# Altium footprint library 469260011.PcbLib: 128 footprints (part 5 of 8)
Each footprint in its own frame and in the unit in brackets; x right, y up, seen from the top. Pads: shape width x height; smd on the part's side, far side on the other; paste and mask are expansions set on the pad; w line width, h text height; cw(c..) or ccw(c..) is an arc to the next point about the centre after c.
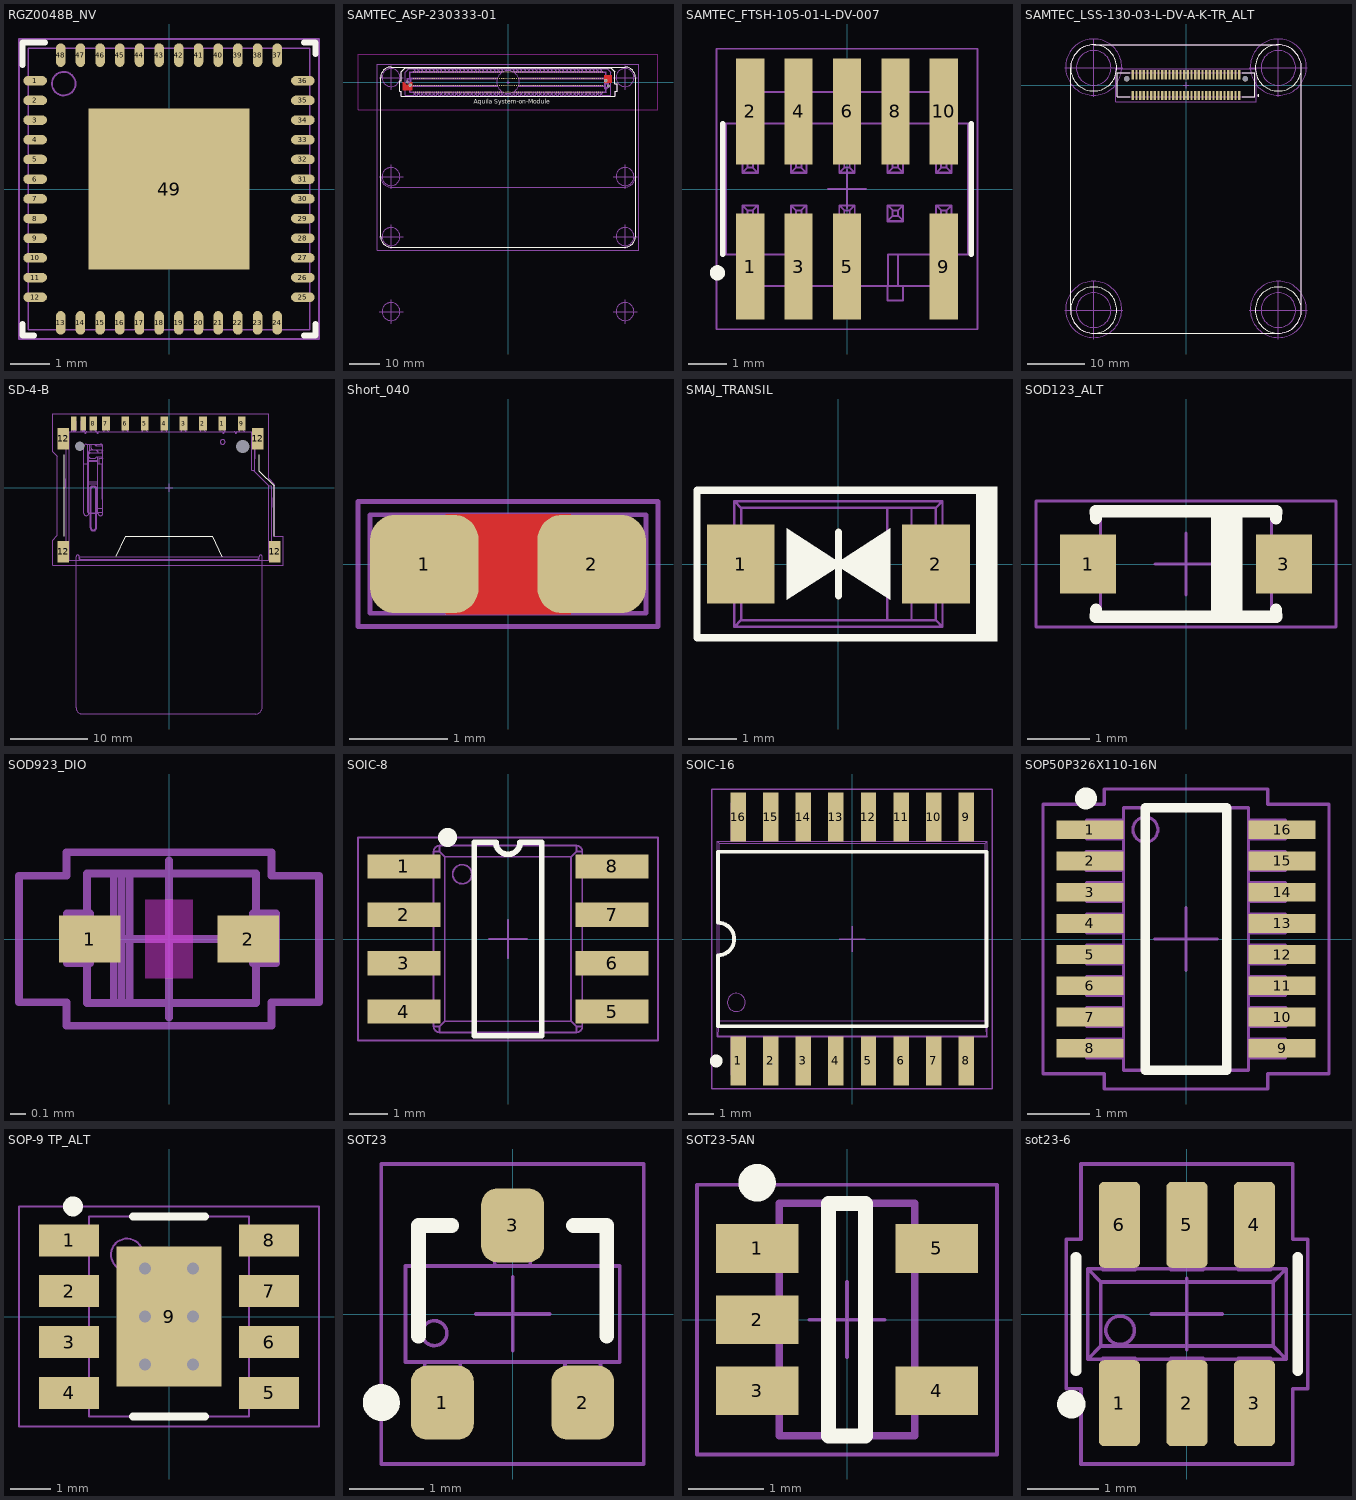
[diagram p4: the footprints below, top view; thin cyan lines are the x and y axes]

## RGZ0048B_NV [mm] "48-VQFN (7x7) (RGZ) Exposed Pad - no vias"
height 1
pads (49):
  oval 0.6x0.24 smd paste+0 mask+0.051: 1(-3.4,2.75) 2(-3.4,2.25) 3(-3.4,1.75) 4(-3.4,1.25) 5(-3.4,0.75) 6(-3.4,0.25) 7(-3.4,-0.25) 8(-3.4,-0.75) 9(-3.4,-1.25) 10(-3.4,-1.75) 11(-3.4,-2.25) 12(-3.4,-2.75) 25(3.4,-2.75) 26(3.4,-2.25) 27(3.4,-1.75) 28(3.4,-1.25) 29(3.4,-0.75) 30(3.4,-0.25) 31(3.4,0.25) 32(3.4,0.75) 33(3.4,1.25) 34(3.4,1.75) 35(3.4,2.25) 36(3.4,2.75)
  oval 0.24x0.6 smd paste+0 mask+0.051: 13(-2.75,-3.4) 14(-2.25,-3.4) 15(-1.75,-3.4) 16(-1.25,-3.4) 17(-0.75,-3.4) 18(-0.25,-3.4) 19(0.25,-3.4) 20(0.75,-3.4) 21(1.25,-3.4) 22(1.75,-3.4) 23(2.25,-3.4) 24(2.75,-3.4) 37(2.75,3.4) 38(2.25,3.4) 39(1.75,3.4) 40(1.25,3.4) 41(0.75,3.4) 42(0.25,3.4) 43(-0.25,3.4) 44(-0.75,3.4) 45(-1.25,3.4) 46(-1.75,3.4) 47(-2.25,3.4) 48(-2.75,3.4)
  rect 4.1x4.1 smd paste-2.037 mask+0.051: 49(0,0)
Top Overlay:
  lines w0.15: -3.725,-3.425 -3.725,-3.725 -3.425,-3.725 ; -3.725,3.15 -3.725,3.725 -3.15,3.725 ; 3.425,-3.725 3.725,-3.725 3.725,-3.425 ; 3.425,3.725 3.725,3.725 3.725,3.425
Top Paste:
  region: 0.1,-0.1 0.1,-1.835 1.835,-1.835 1.835,-0.1
  region: -0.1,-1.835 -0.1,-0.1 -1.835,-0.1 -1.835,-1.835
  region: -0.1,0.1 -0.1,1.835 -1.835,1.835 -1.835,0.1
  region: 0.1,1.835 0.1,0.1 1.835,0.1 1.835,1.835
Top Assembly:
  circle w0.05: c-2.675,2.675 r0.3
  lines w0.05: -3.575,-3.575 3.575,-3.575 3.575,3.575 -3.575,3.575 -3.575,-3.575
  text ".Designator" at -2.252,-0.226 h1
Top Courtyard:
  lines w0.05: -3.81,-3.048 -3.81,-3.81 ; -0.5,0 0.5,0 ; 0,-0.5 0,0.5 ; -3.81,-3.81 -3.81,3.81 3.81,3.81 3.81,-3.81 -3.81,-3.81
3D body "XCVR_DP83867ERGZT.step": height 1, standoff 0, extent -3.5,-3.5 3.5,3.5

## SAMTEC_ASP-230333-01 [mm] "Carrier Plug COM-HPC, 400 pin"
height 5
pads (446):
  round 0.025 on Mech1: 1(-36.106,-3.1) 1(-36.106,-3.1) 1(-36.106,0.475) 1(-36.106,0.475) 1(-35.606,-4.8) 1(-35.606,-4.8) 1(-35.606,-3.1) 1(-35.606,-3.1) 1(-35.606,0.475) 1(-35.606,0.475) 1(-35.606,3.4) 1(-35.606,3.4) 1(-34.206,4.8) 1(-34.206,4.8) 1(-0.506,0) 1(-0.356,0) 1(-0.006,-0.5) 1(0.344,0) 1(34.194,4.8) 1(34.194,4.8) 1(35.594,-3.1) 1(35.594,-0.5) 1(35.594,-4.8) 1(35.594,-4.8) 1(35.594,-3.1) 1(35.594,-0.5) 1(35.594,3.4) 1(35.594,3.4) 1(36.394,-0.5) 1(36.394,-0.5)
  round 0.025 on Top Overlay: 1(-36.106,-3.1) 1(-36.106,-3.1) 1(-35.606,-4.8) 1(-35.606,-4.8) 1(-35.606,-3.1) 1(-35.606,-3.1) 1(-35.606,0.475) 1(-35.606,0.475) 1(35.594,-3.1) 1(35.594,-0.5) 1(35.594,-3.1) 1(35.594,-0.5)
  round 0.356 smd: A01(31.427,3.4) A02(30.792,3.4) A03(30.157,3.4) A04(29.522,3.4) A05(28.887,3.4) A06(28.252,3.4) A07(27.617,3.4) A08(26.982,3.4) A09(26.346,3.4) A10(25.712,3.4) A11(25.077,3.4) A12(24.442,3.4) A13(23.807,3.4) A14(23.172,3.4) A15(22.537,3.4) A16(21.902,3.4) A17(21.267,3.4) A18(20.632,3.4) A19(19.997,3.4) A20(19.362,3.4) A21(18.727,3.4) A22(18.092,3.4) A23(17.457,3.4) A24(16.822,3.4) A25(16.187,3.4) A26(15.552,3.4) A27(14.917,3.4) A28(14.282,3.4) A29(13.647,3.4) A30(13.012,3.4) A31(12.377,3.4) A32(11.742,3.4) A33(11.107,3.4) A34(10.472,3.4) A35(9.837,3.4) A36(9.202,3.4) A37(8.567,3.4) A38(7.932,3.4) A39(7.297,3.4) A40(6.662,3.4) A41(6.027,3.4) A42(5.392,3.4) A43(4.757,3.4) A44(4.122,3.4) A45(3.487,3.4) A46(2.852,3.4) A47(2.217,3.4) A48(1.582,3.4) A49(0.947,3.4) A50(0.312,3.4) A51(-0.323,3.4) A52(-0.958,3.4) A53(-1.593,3.4) A54(-2.228,3.4) A55(-2.863,3.4) A56(-3.498,3.4) A57(-4.133,3.4) A58(-4.768,3.4) A59(-5.403,3.4) A60(-6.038,3.4) A61(-6.673,3.4) A62(-7.308,3.4) A63(-7.943,3.4) A64(-8.578,3.4) A65(-9.213,3.4) A66(-9.848,3.4) A67(-10.483,3.4) A68(-11.118,3.4) A69(-11.753,3.4) A70(-12.388,3.4) A71(-13.023,3.4) A72(-13.658,3.4) A73(-14.293,3.4) A74(-14.928,3.4) A75(-15.563,3.4) A76(-16.198,3.4) A77(-16.833,3.4) A78(-17.468,3.4) A79(-18.103,3.4) A80(-18.738,3.4) A81(-19.373,3.4) A82(-20.008,3.4) A83(-20.643,3.4) A84(-21.278,3.4) A85(-21.913,3.4) A86(-22.548,3.4) A87(-23.183,3.4) A88(-23.818,3.4) A89(-24.453,3.4) A90(-25.088,3.4) A91(-25.723,3.4) A92(-26.358,3.4) A93(-26.993,3.4) A94(-27.628,3.4) A95(-28.263,3.4) A96(-28.898,3.4) A97(-29.533,3.4) A98(-30.168,3.4) A99(-30.803,3.4) A100(-31.438,3.4) B01(31.426,1.2) B02(30.791,1.2) B03(30.156,1.2) B04(29.521,1.2) B05(28.886,1.2) B06(28.251,1.2) B07(27.616,1.2) B08(26.981,1.2) B09(26.346,1.2) B10(25.711,1.2) B11(25.076,1.2) B12(24.441,1.2) B13(23.806,1.2) B14(23.171,1.2) B15(22.536,1.2) B16(21.901,1.2) B17(21.266,1.2) B18(20.631,1.2) B19(19.996,1.2) B20(19.361,1.2) B21(18.726,1.2) B22(18.091,1.2) B23(17.456,1.2) B24(16.821,1.2) B25(16.186,1.2) B26(15.551,1.2) B27(14.916,1.2) B28(14.281,1.2) B29(13.646,1.2) B30(13.011,1.2) B31(12.376,1.2) B32(11.741,1.2) B33(11.106,1.2) B34(10.471,1.2) B35(9.836,1.2) B36(9.201,1.2) B37(8.566,1.2) B38(7.931,1.2) B39(7.296,1.2) B40(6.661,1.2) B41(6.026,1.2) B42(5.391,1.2) B43(4.756,1.2) B44(4.121,1.2) B45(3.486,1.2) B46(2.851,1.2) B47(2.216,1.2) B48(1.581,1.2) B49(0.946,1.2) B50(0.311,1.2) B51(-0.324,1.2) B52(-0.959,1.2) B53(-1.594,1.2) B54(-2.229,1.2) B55(-2.864,1.2) B56(-3.499,1.2) B57(-4.134,1.2) B58(-4.769,1.2) B59(-5.404,1.2) B60(-6.039,1.2) B61(-6.674,1.2) B62(-7.309,1.2) B63(-7.944,1.2) B64(-8.579,1.2) B65(-9.214,1.2) B66(-9.849,1.2) B67(-10.484,1.2) B68(-11.119,1.2) B69(-11.754,1.2) B70(-12.389,1.2) B71(-13.024,1.2) B72(-13.659,1.2) B73(-14.294,1.2) B74(-14.929,1.2) B75(-15.564,1.2) B76(-16.199,1.2) B77(-16.834,1.2) B78(-17.469,1.2) B79(-18.104,1.2) B80(-18.739,1.2) B81(-19.374,1.2) B82(-20.009,1.2) B83(-20.644,1.2) B84(-21.279,1.2) B85(-21.914,1.2) B86(-22.549,1.2) B87(-23.184,1.2) B88(-23.819,1.2) B89(-24.454,1.2) B90(-25.089,1.2) B91(-25.724,1.2) B92(-26.359,1.2) B93(-26.994,1.2) B94(-27.629,1.2) B95(-28.264,1.2) B96(-28.899,1.2) B97(-29.534,1.2) B98(-30.169,1.2) B99(-30.804,1.2) B100(-31.439,1.2) C01(31.426,-1.2) C02(30.791,-1.2) C03(30.156,-1.2) C04(29.521,-1.2) C05(28.886,-1.2) C06(28.251,-1.2) C07(27.616,-1.2) C08(26.981,-1.2) C09(26.346,-1.2) C10(25.711,-1.2) C11(25.076,-1.2) C12(24.441,-1.2) C13(23.806,-1.2) C14(23.171,-1.2) C15(22.536,-1.2) C16(21.901,-1.2) C17(21.266,-1.2) C18(20.631,-1.2) C19(19.996,-1.2) C20(19.361,-1.2) C21(18.726,-1.2) C22(18.091,-1.2) C23(17.456,-1.2) C24(16.821,-1.2) C25(16.186,-1.2) C26(15.551,-1.2) C27(14.916,-1.2) C28(14.281,-1.2) C29(13.646,-1.2) C30(13.011,-1.2) C31(12.376,-1.2) C32(11.741,-1.2) C33(11.106,-1.2) C34(10.471,-1.2) C35(9.836,-1.2) C36(9.201,-1.2) C37(8.566,-1.2) C38(7.931,-1.2) C39(7.296,-1.2) C40(6.661,-1.2) C41(6.026,-1.2) C42(5.391,-1.2) C43(4.756,-1.2) C44(4.121,-1.2) C45(3.486,-1.2) C46(2.851,-1.2) C47(2.216,-1.2) C48(1.581,-1.2) C49(0.946,-1.2) C50(0.311,-1.2) C51(-0.324,-1.2) C52(-0.959,-1.2) C53(-1.594,-1.2) C54(-2.229,-1.2) C55(-2.864,-1.2) C56(-3.499,-1.2) C57(-4.134,-1.2) C58(-4.769,-1.2) C59(-5.404,-1.2) C60(-6.039,-1.2) C61(-6.674,-1.2) C62(-7.309,-1.2) C63(-7.944,-1.2) C64(-8.579,-1.2) C65(-9.214,-1.2) C66(-9.849,-1.2) C67(-10.484,-1.2) C68(-11.119,-1.2) C69(-11.754,-1.2) C70(-12.389,-1.2) C71(-13.024,-1.2) C72(-13.659,-1.2) C73(-14.294,-1.2) C74(-14.929,-1.2) C75(-15.564,-1.2) C76(-16.199,-1.2) C77(-16.834,-1.2) C78(-17.469,-1.2) C79(-18.104,-1.2) C80(-18.739,-1.2) C81(-19.374,-1.2) C82(-20.009,-1.2) C83(-20.644,-1.2) C84(-21.279,-1.2) C85(-21.914,-1.2) C86(-22.549,-1.2) C87(-23.184,-1.2) C88(-23.819,-1.2) C89(-24.454,-1.2) C90(-25.089,-1.2) C91(-25.724,-1.2) C92(-26.359,-1.2) C93(-26.994,-1.2) C94(-27.629,-1.2) C95(-28.264,-1.2) C96(-28.899,-1.2) C97(-29.534,-1.2) C98(-30.169,-1.2) C99(-30.804,-1.2) C100(-31.439,-1.2) D01(31.426,-3.4) D02(30.791,-3.4) D03(30.156,-3.4) D04(29.521,-3.4) D05(28.886,-3.4) D06(28.251,-3.4) D07(27.616,-3.4) D08(26.981,-3.4) D09(26.346,-3.4) D10(25.711,-3.4) D11(25.076,-3.4) D12(24.441,-3.4) D13(23.806,-3.4) D14(23.171,-3.4) D15(22.536,-3.4) D16(21.901,-3.4) D17(21.266,-3.4) D18(20.631,-3.4) D19(19.996,-3.4) D20(19.361,-3.4) D21(18.726,-3.4) D22(18.091,-3.4) D23(17.456,-3.4) D24(16.821,-3.4) D25(16.186,-3.4) D26(15.551,-3.4) D27(14.916,-3.4) D28(14.281,-3.4) D29(13.646,-3.4) D30(13.011,-3.4) D31(12.376,-3.4) D32(11.741,-3.4) D33(11.106,-3.4) D34(10.471,-3.4) D35(9.836,-3.4) D36(9.201,-3.4) D37(8.566,-3.4) D38(7.931,-3.4) D39(7.296,-3.4) D40(6.661,-3.4) D41(6.026,-3.4) D42(5.391,-3.4) D43(4.756,-3.4) D44(4.121,-3.4) D45(3.486,-3.4) D46(2.851,-3.4) D47(2.216,-3.4) D48(1.581,-3.4) D49(0.946,-3.4) D50(0.311,-3.4) D51(-0.324,-3.4) D52(-0.959,-3.4) D53(-1.594,-3.4) D54(-2.229,-3.4) D55(-2.864,-3.4) D56(-3.499,-3.4) D57(-4.134,-3.4) D58(-4.769,-3.4) D59(-5.404,-3.4) D60(-6.039,-3.4) D61(-6.674,-3.4) D62(-7.309,-3.4) D63(-7.944,-3.4) D64(-8.579,-3.4) D65(-9.214,-3.4) D66(-9.849,-3.4) D67(-10.484,-3.4) D68(-11.119,-3.4) D69(-11.754,-3.4) D70(-12.389,-3.4) D71(-13.024,-3.4) D72(-13.659,-3.4) D73(-14.294,-3.4) D74(-14.929,-3.4) D75(-15.564,-3.4) D76(-16.199,-3.4) D77(-16.834,-3.4) D78(-17.469,-3.4) D79(-18.104,-3.4) D80(-18.739,-3.4) D81(-19.374,-3.4) D82(-20.009,-3.4) D83(-20.644,-3.4) D84(-21.279,-3.4) D85(-21.914,-3.4) D86(-22.549,-3.4) D87(-23.184,-3.4) D88(-23.819,-3.4) D89(-24.454,-3.4) D90(-25.089,-3.4) D91(-25.724,-3.4) D92(-26.359,-3.4) D93(-26.994,-3.4) D94(-27.629,-3.4) D95(-28.264,-3.4) D96(-28.899,-3.4) D97(-29.534,-3.4) D98(-30.169,-3.4) D99(-30.804,-3.4) D100(-31.439,-3.4)
  round 0 hole 0.8 unplated paste+0 mask+0.15: MH1(33.556,-1.3)
  round 0 hole 0.6 slot 0.8 at 90 deg unplated paste+0 mask+0.15: MH2(-33.556,0)
  round 1.2 hole 0.8: MH3(32.615,0.5) MH4(-32.615,-1)
Top Layer:
  rectangle: 32,-0.3 34.7,2.4
  region: -35.15,-2.75 -35.15,-0.1 -34.625,-0.1 -33.845,-0.88 -33.28,-0.88 -32.5,-0.1 -32,-0.1 -32,-2.75
Top Layer keep-out:
  lines w0.005: -50.006,-9.2 -50.006,-9.2 ; -50.006,-9.2 -50.006,9.2 49.994,9.2 49.994,-9.2 ; -50.006,-9.2 49.994,-9.2 ; 49.994,-9.2 49.994,-9.2
Top Overlay:
  lines w0.15: 42.494,-31.5 42.494,1.5 ; -42.506,1.5 cw(c-39.006,1.5) -39.006,5 ; -42.506,1.5 cw(c-39.006,1.5) -39.006,5 ; -42.506,1.5 -42.506,-51.5 ccw(c-39.006,-51.5) -39.006,-55 38.994,-55 ccw(c38.994,-51.5) 42.494,-51.5 42.494,1.5 ; -39.006,5 38.994,5 ; -39.006,5 38.994,5 ; 38.994,5 cw(c38.994,1.5) 42.494,1.5 ; 38.994,5 cw(c38.994,1.5) 42.494,1.5 ; -36.106,-3.1 -36.106,0.475 -35.606,0.475 -35.606,3.4 -34.206,4.8 34.194,4.8 35.594,3.4 35.594,-0.5 36.394,-0.5 36.394,-3.1 35.594,-3.1 35.594,-4.8 -35.606,-4.8 -35.606,-3.1 -36.106,-3.1
  text "Aquila System-on-Module" at -11.497,-7.755 h2.5
Mechanical 1:
  circle w0.05: c-39.006,-76.5 r3
  circle w0.05: c-39.006,1.5 r3
  circle w0.05: c-39.006,-31.5 r3
  circle w0.05: c38.994,-31.5 r3
  circle w0.05: c38.994,-76.5 r3
  circle w0.05: c38.994,1.5 r3
  circle w0.05: c-39.006,-51.5 r3
  circle w0.05: c38.994,-51.5 r3
  lines w0.05: -43.006,-76.5 -35.006,-76.5 ; -43.006,-51.5 -35.006,-51.5 ; -43.006,-31.5 -35.006,-31.5 ; -43.006,1.5 -35.006,1.5 ; -39.006,-80.5 -39.006,-72.5 ; -39.006,-55.5 -39.006,-47.5 ; -39.006,-35.5 -39.006,-27.5 ; -39.006,-2.5 -39.006,5.5 ; -0.506,0 0.494,0 ; -0.006,-0.5 -0.006,0.5 ; 34.994,-76.5 42.994,-76.5 ; 34.994,-51.5 42.994,-51.5 ; 34.994,-31.5 42.994,-31.5 ; 34.994,1.5 42.994,1.5 ; 38.95,5.5 39,5.5 ; 38.994,-80.5 38.994,-72.5 ; 38.994,-55.5 38.994,-47.5 ; 38.994,-35.5 38.994,-27.5 ; 38.994,-2.5 38.994,5.5 ; -42.506,1.5 cw(c-39.006,1.5) -39.006,5 ; -42.506,1.5 cw(c-39.006,1.5) -39.006,5 ; -42.506,1.5 -42.506,-51.5 ccw(c-39.006,-51.5) -39.006,-55 38.994,-55 ccw(c38.994,-51.5) 42.494,-51.5 42.494,1.5 ; -42.506,1.5 -42.506,-31.5 ccw(c-39.006,-31.5) -39.006,-35 38.994,-35 ccw(c38.994,-31.5) 42.494,-31.5 42.494,1.5 ; -39.006,5 38.994,5 ; -39.006,5 38.994,5 ; 38.994,5 cw(c38.994,1.5) 42.494,1.5 ; 38.994,5 cw(c38.994,1.5) 42.494,1.5 ; -36.106,-3.1 -36.106,0.475 -35.606,0.475 -35.606,3.4 -34.206,4.8 34.194,4.8 35.594,3.4 35.594,-0.5 36.394,-0.5 36.394,-3.1 35.594,-3.1 35.594,-4.8 -35.606,-4.8 -35.606,-3.1 -36.106,-3.1
Top Assembly:
  drawing of 6432 lines, arcs and shapes, not listed
  text ".Designator" at -2.258,-0.226 h1
Top Courtyard:
  lines w0.05: -0.506,0 0.494,0 ; -0.006,-0.5 -0.006,0.5 ; -43.55,-56 43.55,-56 43.55,6 -43.55,6 -43.55,-56
3D body "11-ASP-230333-004.step": height 4.1, standoff -1.33, extent -34.314,-4.375 34.302,4.375

## SAMTEC_FTSH-105-01-L-DV-007 [mm]
pads (9):
  rect 0.74x2.79 smd: 1(-2.54,-2.035) 2(-2.54,2.035) 3(-1.27,-2.035) 4(-1.27,2.035) 5(0,-2.035) 6(0,2.035) 8(1.27,2.035) 9(2.54,-2.035) 10(2.54,2.035)
Top Overlay:
  circle w0.2: c-3.4,-2.2 r0.1
  lines w0.15: -3.26,-1.715 -3.26,1.715 ; 3.26,-1.715 3.26,1.715
Top Assembly:
  drawing of 175 lines, arcs and shapes, not listed
  text ".Designator" at -2.252,-0.226 h1
Top Courtyard:
  lines w0.05: -0.5,0 0.5,0 ; 0,-0.5 0,0.5 ; -3.425,-3.68 -3.425,3.68 3.425,3.68 3.425,-3.68 -3.425,-3.68
3D body "FTSH-105-01-L-DV-007-K.stp": height 6.02, standoff -0.1, extent -3.188,-2.908 3.162,2.934

## SAMTEC_LSS-130-03-L-DV-A-K-TR_ALT [mm] "For DSI mezzanine board"
pads (62):
  rect 0.4x1.6 smd: 1(9.207,-1.8) 2(9.207,1.8) 3(8.572,-1.8) 4(8.572,1.8) 5(7.938,-1.8) 6(7.938,1.8) 7(7.302,-1.8) 8(7.302,1.8) 9(6.667,-1.8) 10(6.667,1.8) 11(6.032,-1.8) 12(6.032,1.8) 13(5.397,-1.8) 14(5.397,1.8) 15(4.763,-1.8) 16(4.763,1.8) 17(4.127,-1.8) 18(4.127,1.8) 19(3.492,-1.8) 20(3.492,1.8) 21(2.857,-1.8) 22(2.857,1.8) 23(2.222,-1.8) 24(2.222,1.8) 25(1.587,-1.8) 26(1.587,1.8) 27(0.953,-1.8) 28(0.953,1.8) 29(0.318,-1.8) 30(0.318,1.8) 31(-0.318,-1.8) 32(-0.318,1.8) 33(-0.953,-1.8) 34(-0.953,1.8) 35(-1.587,-1.8) 36(-1.587,1.8) 37(-2.222,-1.8) 38(-2.222,1.8) 39(-2.857,-1.8) 40(-2.857,1.8) 41(-3.492,-1.8) 42(-3.492,1.8) 43(-4.127,-1.8) 44(-4.127,1.8) 45(-4.763,-1.8) 46(-4.763,1.8) 47(-5.397,-1.8) 48(-5.397,1.8) 49(-6.032,-1.8) 50(-6.032,1.8) 51(-6.667,-1.8) 52(-6.667,1.8) 53(-7.302,-1.8) 54(-7.302,1.8) 55(-7.938,-1.8) 56(-7.938,1.8) 57(-8.572,-1.8) 58(-8.572,1.8) 59(-9.207,-1.8) 60(-9.207,1.8)
  round 0.89 hole 0.89 unplated: ""(-10.275,1.1) ""(10.275,1.1)
Top Overlay:
  circle w0.2: c12.55,-1.8 r0.1
  lines w0.15: -9.757,-2 -11.9,-2 -11.9,2.14 -9.757,2.14 ; 9.757,-2 11.9,-2 11.9,2.14 9.757,2.14 ; -16,-43 cw(c-16,-39) -16,-35 cw(c-16,-39) -16,-43 ; -16,-43 cw(c-16,-39) -20,-39 -20,3 cw(c-16,3) -16,7 ; -16,-43 16,-43 ; -16,7 ccw(c-16,3) -16,-1 ccw(c-16,3) -16,7 ; -16,7 16,7 ; 16,-43 cw(c16,-39) 16,-35 cw(c16,-39) 16,-43 ; 16,-43 ccw(c16,-39) 20,-39 20,3 ccw(c16,3) 16,7 ; 16,7 ccw(c16,3) 16,-1 ccw(c16,3) 16,7
Mechanical 1:
  lines w0.05: -21,-39 -11,-39 ; -21,3 -11,3 ; -16,-44 -16,-34 ; -16,-2 -16,8 ; 11,-39 21,-39 ; 11,3 21,3 ; 16,-44 16,-34 ; 16,-2 16,8 ; -20,-39 ccw(c-16,-39) -16,-43 16,-43 ccw(c16,-39) 20,-39 20,3 ccw(c16,3) 16,7 -16,7 ccw(c-16,3) -20,3 -20,-39 ; -16,-42 ccw(c-16,-39) -16,-36 ccw(c-16,-39) -16,-42 ; -16,0 cw(c-16,3) -16,6 cw(c-16,3) -16,0 ; 16,-42 cw(c16,-39) 16,-36 cw(c16,-39) 16,-42 ; 16,0 cw(c16,3) 16,6 cw(c16,3) 16,0
Top 3D Body:
  circle w0.2: c12.55,-1.8 r0.1
  lines w0.1: -11.9,-2 -11.9,2.14 ; -11.9,-2 11.9,-2 ; -11.9,-2 -11.9,2.14 ; -11.9,2.14 11.9,2.14 ; -11.9,2.14 11.9,2.14 ; 11.9,-2 11.9,2.14 ; 11.9,-2 11.9,2.14
Top Assembly:
  lines w0.05: -20,-39 ccw(c-16,-39) -16,-43 16,-43 ccw(c16,-39) 20,-39 20,3 ccw(c16,3) 16,7 -16,7 ccw(c-16,3) -20,3 -20,-39
  text ".Designator" at -2.252,-0.226 h1
Top Courtyard:
  lines w0.05: -0.5,0 0.5,0 ; 0,-0.5 0,0.5 ; -16,-43.75 cw(c-16,-38.875) -16,-34 cw(c-16,-38.875) -16,-43.75 ; -16,-1.75 cw(c-16,3.125) -16,8 cw(c-16,3.125) -16,-1.75 ; -12.15,-2.85 -12.15,2.85 12.15,2.85 12.15,-2.85 -12.15,-2.85 ; 16,-43.75 cw(c16,-38.875) 16,-34 cw(c16,-38.875) 16,-43.75 ; 16,-1.75 cw(c16,3.125) 16,8 cw(c16,3.125) 16,-1.75
3D body "LSS-130-03-L-DV-A-K-TR.stp": height 5.39, standoff -1, extent -11.897,-2.325 11.903,2.472

## SD-4-B [mm] "SD Card Connector, 11 Positions, Connector, Push In, Pull Out, Surface Mount, 2.8 mm Height Above Board, Gold Flash"
height 2.8
pads (17):
  round 0 hole 1.2 unplated: 0(-11.5,5.325)
  rect 1x1.8 smd: 1(6.875,8.275) 2(4.375,8.275) 3(1.875,8.275) 4(-0.625,8.275) 5(-3.125,8.275) 6(-5.625,8.275) 7(-8.125,8.275) 8(-9.755,8.275) 9(9.375,8.275)
  round 0 hole 1.7 unplated: 3(9.5,5.325)
  rect 0.7x1.8 smd: 10(-11.055,8.275) 11(-12.255,8.275)
  rect 1.5x2.8 smd: 12(-13.65,-8.275) 12(-13.65,6.325) 12(11.42,6.325) 12(13.65,-8.275)
Top Overlay:
  lines w0.15: -13.5,-6.25 -13.5,4.25 ; -6.786,-8.868 -5.575,-6.25 5.575,-6.25 6.793,-8.884 ; 11.66,4.25 11.66,2.14 13.55,0.25 13.55,-6.24
Top Assembly:
  drawing of 2004 lines, arcs and shapes, not listed
  text ".Designator" at -2.252,-0.226 h1
  text "SD CARD EDGE" at -3.358,-28.745 h1
Top Courtyard:
  lines w0.05: -0.5,0 0.5,0 ; 0,-0.5 0,0.5 ; -15,-10 14.75,-10 14.75,-6.24 13.6,-6.24 13.6,0.449 12.86,1.189 12.86,9.5 -15,9.5 -15,4.625 -14.4,4.025 -14.4,-6.15 -15,-6.75 -15,-10
3D body "693063020911.stp": height 3.52, standoff -0.48, extent -13.84,-9.225 13.81,8.775

## Short_040 [mm]
height 0.5
pads (2):
  rrect50% 1.1x1 smd paste-2539.97 mask-2539.97: 1(-0.85,0) 2(0.85,0)
Top Layer:
  region: -1.143,-0.381 1.143,-0.381 1.143,0.381 -1.143,0.381
  pour cut-out: -0.635,-0.508 0.635,-0.508 0.635,0.508 -0.635,0.508
Top Solder:
  region: -1.5,-0.325 -1.5,0.325 -1.5,0.357 -1.488,0.42 -1.463,0.479 -1.427,0.532 -1.382,0.577 -1.329,0.613 -1.27,0.638 -1.207,0.65 -1.175,0.65 -0.525,0.65 -0.493,0.65 -0.43,0.638 -0.371,0.613 -0.318,0.577 -0.273,0.532 -0.237,0.479 -0.212,0.42 -0.2,0.357 -0.2,0.325 -0.2,-0.325 -0.2,-0.357 -0.212,-0.42 -0.237,-0.479 -0.273,-0.532 -0.318,-0.577 -0.371,-0.613 -0.43,-0.638 -0.493,-0.65 -0.525,-0.65 -1.175,-0.65 -1.207,-0.65 -1.27,-0.638 -1.329,-0.613 -1.382,-0.577 -1.427,-0.532 -1.463,-0.479 -1.488,-0.42 -1.5,-0.357
  region: 0.2,-0.325 0.2,0.325 0.2,0.357 0.212,0.42 0.237,0.479 0.273,0.532 0.318,0.577 0.371,0.613 0.43,0.638 0.493,0.65 0.525,0.65 1.175,0.65 1.207,0.65 1.27,0.638 1.329,0.613 1.382,0.577 1.427,0.532 1.463,0.479 1.488,0.42 1.5,0.357 1.5,0.325 1.5,-0.325 1.5,-0.357 1.488,-0.42 1.463,-0.479 1.427,-0.532 1.382,-0.577 1.329,-0.613 1.27,-0.638 1.207,-0.65 1.175,-0.65 0.525,-0.65 0.493,-0.65 0.43,-0.638 0.371,-0.613 0.318,-0.577 0.273,-0.532 0.237,-0.479 0.212,-0.42 0.2,-0.357
Top Assembly:
  lines w0.05: -1.4,-0.5 -1.4,0.5 1.4,0.5 1.4,-0.5 -1.4,-0.5
  text ".Designator" at -2.252,-0.226 h1
Top Courtyard:
  lines w0.05: -0.5,0 0.5,0 ; 0,-0.5 0,0.5 ; -1.524,-0.635 1.524,-0.635 1.524,0.635 -1.524,0.635 -1.524,-0.635

## SMAJ_TRANSIL [mm] "Diode SMA J-lead Transil / DO-214AC SMA"
height 2.95
pads (2):
  rect 1.4x1.64 smd: 1(-2.015,0) 2(2.015,0)
Top Overlay:
  region: 1.067,-0.737 -0.076,0 1.067,0.737
  region: 2.845,1.6 3.277,1.6 3.277,-1.6 2.845,-1.6
  region: -1.067,0.737 0.076,0 -1.067,-0.737
  lines w0.15: 0,-0.66 0,0.66 ; -2.921,-1.524 2.921,-1.524 2.921,1.524 -2.921,1.524 -2.921,-1.524
Top Assembly:
  lines w0.05: -2.45,-0.75 -2.45,0.75 ; -2.45,-0.75 -2.6,-0.75 -2.6,0.75 -2.45,0.75 ; -2.45,-0.75 -2.15,-0.75 ; -2.45,0.75 -2.15,0.75 ; -2.15,-1.3 -2.011,-1.159 ; -2.15,-1.3 2.15,-1.3 ; -2.15,-1.3 -2.15,-0.75 ; -2.15,-0.75 -2.15,0.75 ; -2.15,0.75 -2.15,1.3 ; -2.15,1.3 2.15,1.3 ; -2.15,1.3 -2.011,1.159 ; -2.011,-1.159 1.011,-1.159 ; -2.011,-1.159 -2.011,1.159 ; -2.011,1.159 1.011,1.159 ; 1.011,-1.159 1.011,1.159 ; 1.011,-1.159 1.511,-1.159 ; 1.011,1.159 1.511,1.159 ; 1.511,-1.159 1.511,1.159 ; 1.511,-1.159 2.011,-1.159 ; 1.511,1.159 2.011,1.159 ; 2.011,-1.159 2.011,1.159 ; 2.011,-1.159 2.15,-1.3 ; 2.011,1.159 2.15,1.3 ; 2.15,-1.3 2.15,-0.75 ; 2.15,-0.75 2.15,0.75 ; 2.15,-0.75 2.45,-0.75 ; 2.15,0.75 2.45,0.75 ; 2.15,0.75 2.15,1.3 ; 2.45,-0.75 2.6,-0.75 2.6,0.75 2.45,0.75 ; 2.45,-0.75 2.45,0.75
  text ".Designator" at -2.252,-0.226 h1
Top Courtyard:
  lines w0.05: -0.3,0 0.3,0 ; 0,-0.3 0,0.3 ; -2.921,-1.524 3.099,-1.524 3.099,1.524 -2.921,1.524 -2.921,-1.524
3D body "User Library-DO-214AC SMA.step": height 2.4, standoff 0, extent -2.6,-1.3 2.6,1.3

## SOD123_ALT [mm] "SOD-123; 2 Leads; Body 2.7 x 1.6 mm, (LxW)"
height 1.35
pads (2):
  rect 0.9x0.95 smd: 1(-1.575,0) 3(1.575,0)
Top Overlay:
  region: 0.5,0.85 0.5,-0.85 0.909,-0.85 0.909,0.85 0.809,0.85
  lines w0.2: -1.448,-0.737 -1.45,-0.85 1.45,-0.85 1.448,-0.737 ; -1.448,0.737 -1.45,0.85 1.45,0.85 1.448,0.737 ; 0.5,-0.85 0.5,0.85
Top Assembly:
  lines w0.05: 0.536,-0.8 0.536,0.8 ; 0.576,-0.805 0.576,0.795 ; 0.601,-0.805 0.601,0.795 ; 0.627,-0.805 0.627,0.795 ; 0.652,-0.805 0.652,0.795 ; 0.678,-0.805 0.678,0.795 ; -1.85,-0.3 -1.85,0.3 ; -1.85,-0.3 -1.375,-0.3 ; -1.85,-0.3 -1.85,0.3 ; -1.85,-0.3 -1.55,-0.3 ; -1.85,0.3 -1.375,0.3 ; -1.85,0.3 -1.55,0.3 ; -1.55,-0.3 -1.55,0.3 ; -1.55,-0.3 -1.375,-0.3 ; -1.55,0.3 -1.375,0.3 ; -1.375,-0.8 -1.375,-0.3 ; -1.375,-0.8 1.375,-0.8 ; -1.375,-0.8 1.375,-0.8 ; -1.375,-0.8 -1.375,0.8 ; -1.375,0.3 -1.375,0.8 ; -1.375,0.8 1.375,0.8 ; -1.375,0.8 1.375,0.8 ; 1.375,-0.8 1.375,-0.3 ; 1.375,-0.8 1.375,0.8 ; 1.375,-0.3 1.85,-0.3 ; 1.375,-0.3 1.55,-0.3 ; 1.375,0.3 1.85,0.3 ; 1.375,0.3 1.375,0.8 ; 1.375,0.3 1.55,0.3 ; 1.55,-0.3 1.55,0.3 ; 1.55,-0.3 1.85,-0.3 ; 1.55,0.3 1.85,0.3 ; 1.85,-0.3 1.85,0.3 ; 1.85,-0.3 1.85,0.3
  text ".Designator" at -2.252,-0.226 h1
Top Courtyard:
  lines w0.05: -0.5,0 0.5,0 ; 0,-0.5 0,0.5 ; -2.413,-1.016 -2.413,1.016 2.413,1.016 2.413,-1.016 -2.413,-1.016
3D body "User Library-SOD123.step": height 1.27, standoff 0, extent -1.85,-0.8 1.85,0.8

## SOD923_DIO [mm] "Diode, SOD-923, CASE 514AA"
height 0.5
pads (2):
  rect 0.393x0.3 smd paste+0 mask+0: 1(-0.507,0) 2(0.507,0)
Top Layer keep-out:
  region: -0.15,-0.249 -0.15,0.249 0.15,0.249 0.15,-0.249
Top Assembly:
  lines w0.05: -0.524,-0.154 -0.524,-0.408 0.555,-0.408 0.555,-0.154 ; -0.524,0.163 -0.524,0.417 0.555,0.417 0.555,0.163 ; -0.352,-0.408 -0.352,0.417 ; -0.302,-0.408 -0.302,0.417 ; -0.251,-0.408 -0.251,0.417 ; -0.651,-0.154 -0.505,-0.154 -0.505,0.163 -0.651,0.163 -0.651,-0.154 ; 0.537,-0.154 0.683,-0.154 0.683,0.163 0.537,0.163 0.537,-0.154
  text ".Designator" at -2.252,-0.226 h1
Top Courtyard:
  lines w0.05: -0.5,0 0.5,0 ; 0,-0.5 0,0.5 ; -0.957,-0.404 -0.654,-0.404 -0.654,-0.554 0.654,-0.554 0.654,-0.404 0.957,-0.404 0.957,0.404 0.654,0.404 0.654,0.554 -0.654,0.554 -0.654,0.404 -0.957,0.404 -0.957,-0.404
3D body "User Library-DIODE_SOD-923.step": height 0.43, standoff 0, extent -0.525,-0.325 0.525,0.325

## SOIC-8 [mil] "8-SOIC (0.154\", 3.90mm Width)"
height 68.9
pads (8):
  rect 75x25 smd: 1(-107.5,75) 2(-107.5,25) 3(-107.5,-25) 4(-107.5,-75) 5(107.5,-75) 6(107.5,-25) 7(107.5,25) 8(107.5,75)
Top Overlay:
  circle w9.84: c-62.42,105 r4.92
  lines w5.91: -35,-100 -35,100 -12.5,100 ccw(c0,100) 12.5,100 35,100 35,-100 -35,-100
Top Assembly:
  drawing of 161 lines, arcs and shapes, not listed
  text ".Designator" at -88.67,-8.9 h39.37
Top Courtyard:
  lines w1.97: -19.69,0 19.68,0 ; 0,-19.69 0,19.68 ; -155,-105 155,-105 155,105 -133,105 -155,105 -155,-105
3D body "User Library-so8-3.step": height 66.93, standoff 0, extent -118.11,-96.46 118.11,96.46

## SOIC-16 [mm] "SOIC127P1030X265-16M_[SOIC-16W]_JEDEC_MS-013AA"
height 2.65
pads (16):
  rect 0.6x1.9 smd: 1(-4.445,-4.75) 2(-3.175,-4.75) 3(-1.905,-4.75) 4(-0.635,-4.75) 5(0.635,-4.75) 6(1.905,-4.75) 7(3.175,-4.75) 8(4.445,-4.75) 9(4.445,4.75) 10(3.175,4.75) 11(1.905,4.75) 12(0.635,4.75) 13(-0.635,4.75) 14(-1.905,4.75) 15(-3.175,4.75) 16(-4.445,4.75)
Top Overlay:
  circle w0.25: c-5.295,-4.75 r0.125
  lines w0.15: -5.23,-3.4 -5.23,-0.635 ccw(c-5.23,0) -5.23,0.635 -5.23,3.4 5.23,3.4 5.23,-3.4 -5.23,-3.4
Top Assembly:
  drawing of 288 lines, arcs and shapes, not listed
  text ".Designator" at -2.252,-0.226 h1
Top Courtyard:
  lines w0.05: -0.5,0 0.5,0 ; 0,-0.5 0,0.5 ; -5.461,-5.842 -5.461,5.842 5.461,5.842 5.461,-5.842 -5.461,-5.842
3D body "User Library-SOIC16_Wide_JEDEC_MS-013AA.step": height 2.66, standoff 0.01, extent -5.25,-5.315 5.25,5.315

## SOP50P326X110-16N [mm] "16-SOT-23-THIN"
height 1.1
pads (16):
  rect 1.075x0.3 smd: 1(-1.538,1.75) 2(-1.538,1.25) 3(-1.538,0.75) 4(-1.538,0.25) 5(-1.538,-0.25) 6(-1.538,-0.75) 7(-1.538,-1.25) 8(-1.538,-1.75) 9(1.538,-1.75) 10(1.538,-1.25) 11(1.538,-0.75) 12(1.538,-0.25) 13(1.538,0.25) 14(1.538,0.75) 15(1.538,1.25) 16(1.538,1.75)
Top Overlay:
  circle w0.2: c-1.6,2.25 r0.075
  lines w0.15: -0.65,-2.1 0.65,-2.1 0.65,2.1 -0.65,2.1 -0.65,-2.1
Top Assembly:
  circle w0.05: c-0.65,1.75 r0.2
  lines w0.05: -1.007,1.1 -1.6,1.1 -1.6,1.4 -1.007,1.4 ; -1.001,-1.9 -1.594,-1.9 -1.594,-1.6 -1.001,-1.6 ; -1.001,-1.4 -1.594,-1.4 -1.594,-1.1 -1.001,-1.1 ; -1.001,-0.9 -1.594,-0.9 -1.594,-0.6 -1.001,-0.6 ; -1.001,-0.4 -1.594,-0.4 -1.594,-0.1 -1.001,-0.1 ; -1.001,0.1 -1.594,0.1 -1.594,0.4 -1.001,0.4 ; -1.001,0.6 -1.594,0.6 -1.594,0.9 -1.001,0.9 ; -1.001,1.6 -1.594,1.6 -1.594,1.9 -1.001,1.9 ; 1.001,-1.9 1.594,-1.9 1.594,-1.6 1.001,-1.6 ; 1.001,-0.9 1.594,-0.9 1.594,-0.6 1.001,-0.6 ; 1.001,-0.4 1.594,-0.4 1.594,-0.1 1.001,-0.1 ; 1.001,0.1 1.594,0.1 1.594,0.4 1.001,0.4 ; 1.001,0.6 1.594,0.6 1.594,0.9 1.001,0.9 ; 1.001,1.1 1.594,1.1 1.594,1.4 1.001,1.4 ; 1.001,1.6 1.594,1.6 1.594,1.9 1.001,1.9 ; 1.007,-1.4 1.6,-1.4 1.6,-1.1 1.007,-1.1 ; -1,-2.1 -1,2.1 1,2.1 1,-2.1 -1,-2.1
  text ".Designator" at -2.252,-0.226 h1
Top Courtyard:
  lines w0.05: -0.5,0 0.5,0 ; 0,-0.5 0,0.5 ; -2.286,-2.156 -2.286,2.156 -1.308,2.156 -1.308,2.4 1.308,2.4 1.308,2.156 2.286,2.156 2.286,-2.156 1.308,-2.156 1.308,-2.4 -1.308,-2.4 -1.308,-2.156 -2.286,-2.156
3D body "TMUX1574DYYR.stp": height 0.97, standoff -0.05, extent -1.632,-2.1 1.632,2.1

## SOP-9 TP_ALT [mm] "SOIC, 8-Leads, Body 5,0x4,0mm (max), Pitch 1,27mm, IPC Medium Density"
height 1.75
pads (9):
  rect 1.505x0.802 smd: 1(-2.5,1.905) 2(-2.5,0.635) 3(-2.5,-0.635) 4(-2.5,-1.905) 5(2.5,-1.905) 6(2.5,-0.635) 7(2.5,0.635) 8(2.5,1.905)
  rect 2.613x3.502 smd: 9(0,0)
via 0.6,-1.2 diameter 0.6 hole 0.3
via -0.6,-1.2 diameter 0.6 hole 0.3
via 0.6,0 diameter 0.6 hole 0.3
via -0.6,0 diameter 0.6 hole 0.3
via 0.6,1.2 diameter 0.6 hole 0.3
via -0.6,1.2 diameter 0.6 hole 0.3
Top Overlay:
  circle w0.25: c-2.4,2.755 r0.125
  lines w0.2: -0.9,-2.5 0.9,-2.5 ; -0.9,2.5 0.9,2.5
Top Assembly:
  circle w0.05: c-1.05,1.55 r0.4
  lines w0.05: -2,-2.205 -2.92,-2.205 -2.92,-1.619 -2,-1.619 ; -2,-0.935 -2.92,-0.935 -2.92,-0.349 -2,-0.349 ; -2,0.335 -2.92,0.335 -2.92,0.921 -2,0.921 ; -2,1.605 -2.92,1.605 -2.92,2.191 -2,2.191 ; 2,-2.191 2.92,-2.191 2.92,-1.605 2,-1.605 ; 2,-0.921 2.92,-0.921 2.92,-0.335 2,-0.335 ; 2,0.349 2.92,0.349 2.92,0.935 2,0.935 ; 2,1.619 2.92,1.619 2.92,2.205 2,2.205 ; -2,-2.5 -2,2.5 2,2.5 2,-2.5 -2,-2.5
  text ".Designator" at -2.252,-0.226 h1
Top Courtyard:
  lines w0.05: -0.5,0 0.5,0 ; 0,-0.5 0,0.5 ; -3.75,-2.75 -3.75,2.75 3.75,2.75 3.75,-2.75 -3.75,-2.75
3D body "SO-8EP.STP": height 1.45, standoff -0.1, extent -3.001,-2.451 3.001,2.451

## SOT23 [mm]
height 2.54
pads (3):
  rrect50% 0.85x1 smd: 1(-0.95,-1.2) 2(0.95,-1.2) 3(0,1.2)
Top Overlay:
  circle w0.25: c-1.778,-1.2 r0.125
  lines w0.2: -1.275,-0.3 -1.275,1.2 -0.825,1.2 ; 0.825,1.2 1.275,1.2 1.275,-0.3
Top Assembly:
  circle w0.05: c-1.06,-0.26 r0.169
  lines w0.05: -1.19,-1.19 -1.19,-1.099 ; -1.19,-1.19 -1.19,-1.4 -0.71,-1.4 -0.71,-1.19 ; -1.19,-1.19 -0.71,-1.19 ; -1.19,-1.099 -1.19,-1.074 ; -1.19,-1.099 -0.71,-1.099 ; -1.19,-1.074 -1.19,-0.825 ; -1.19,-1.074 -0.71,-1.074 ; -1.19,-0.825 -1.19,-0.65 ; -1.19,-0.825 -0.71,-0.825 ; -1.19,-0.65 -0.71,-0.65 ; -1.19,-0.65 -1.45,-0.65 -1.45,0.65 -0.24,0.65 ; -0.71,-1.19 -0.71,-1.099 ; -0.71,-1.099 -0.71,-1.074 ; -0.71,-1.074 -0.71,-0.825 ; -0.71,-0.825 -0.71,-0.65 ; -0.71,-0.65 0.71,-0.65 ; -0.24,0.65 0.24,0.65 ; -0.24,0.65 -0.24,0.825 ; -0.24,0.825 -0.24,1.074 ; -0.24,0.825 0.24,0.825 ; -0.24,1.074 -0.24,1.099 ; -0.24,1.074 0.24,1.074 ; -0.24,1.099 -0.24,1.19 ; -0.24,1.099 0.24,1.099 ; -0.24,1.19 -0.24,1.4 0.24,1.4 0.24,1.19 ; -0.24,1.19 0.24,1.19 ; 0.24,0.65 1.45,0.65 1.45,-0.65 1.19,-0.65 ; 0.24,0.65 0.24,0.825 ; 0.24,0.825 0.24,1.074 ; 0.24,1.074 0.24,1.099 ; 0.24,1.099 0.24,1.19 ; 0.71,-1.19 0.71,-1.099 ; 0.71,-1.19 0.71,-1.4 1.19,-1.4 1.19,-1.19 ; 0.71,-1.19 1.19,-1.19 ; 0.71,-1.099 0.71,-1.074 ; 0.71,-1.099 1.19,-1.099 ; 0.71,-1.074 0.71,-0.825 ; 0.71,-1.074 1.19,-1.074 ; 0.71,-0.825 0.71,-0.65 ; 0.71,-0.825 1.19,-0.825 ; 0.71,-0.65 1.19,-0.65 ; 1.19,-1.19 1.19,-1.099 ; 1.19,-1.099 1.19,-1.074 ; 1.19,-1.074 1.19,-0.825 ; 1.19,-0.825 1.19,-0.65
  text ".Designator" at -2.252,-0.226 h1
Top Courtyard:
  lines w0.05: -0.5,0 0.5,0 ; 0,-0.5 0,0.5 ; -1.778,-2.032 1.778,-2.032 1.778,2.032 -1.778,2.032 -1.778,-2.032
3D body "User Library-SOT23-3.step": height 1.3, standoff 0, extent -1.45,-1.4 1.45,1.4

## SOT23-5AN [mm] "SOT23, 5-Leads, Body 2.9x1.6mm, Pitch 0.95mm, Lead Span 2.8mm, IPC Medium Density"
height 1.45
pads (5):
  rect 1.1x0.65 smd: 1(-1.2,0.95) 2(-1.2,0) 3(-1.2,-0.95) 4(1.2,-0.95) 5(1.2,0.95)
Top Overlay:
  circle w0.25: c-1.2,1.825 r0.125
  lines w0.2: -0.25,-1.55 -0.25,1.55 0.25,1.55 0.25,-1.55 -0.25,-1.55
Top 3D Body:
  lines w0.1: -0.9,-1.55 0.9,-1.55 0.9,1.55 -0.9,1.55 -0.9,-1.55
Top Courtyard:
  lines w0.05: -0.5,0 0.5,0 ; 0,-0.5 0,0.5 ; -2,-1.8 2,-1.8 2,1.8 -2,1.8 -2,-1.8
3D body: height 1.45, standoff 0, extent -0.9,-1.55 0.9,1.55

## sot23-6 [mm]
height 1.1
pads (6):
  rrect25% 0.58x1.21 smd: 1(-0.95,-1.255) 2(0,-1.255) 3(0.95,-1.255) 4(0.95,1.255) 5(0,1.255) 6(-0.95,1.255)
Top Overlay:
  circle w0.2: c-1.626,-1.27 r0.1
  lines w0.15: -1.56,-0.8 -1.56,0.8 ; 1.56,-0.8 1.56,0.8
Top Assembly:
  circle w0.05: c-0.94,-0.229 r0.2
  lines w0.05: -1.181,-0.635 -1.397,-0.635 ; -1.181,0.635 -1.397,0.635 ; -0.724,-0.635 -0.229,-0.635 ; -0.724,0.635 -0.229,0.635 ; 0.229,-0.635 0.724,-0.635 ; 0.229,0.635 0.724,0.635 ; 1.181,-0.635 1.397,-0.635 ; 1.181,0.635 1.397,0.635 ; -1.397,-0.635 -1.212,-0.45 ; -1.397,-0.635 -1.397,0.635 ; -1.397,0.635 -1.212,0.45 ; -1.212,-0.45 1.212,-0.45 ; -1.212,-0.45 -1.212,0.45 ; -1.212,0.45 1.212,0.45 ; -1.181,-1.003 -0.724,-1.003 ; -1.181,-1.003 -1.181,-0.927 ; -1.181,-1.003 -1.181,-1.206 -0.724,-1.206 -0.724,-1.003 ; -1.181,-0.927 -0.724,-0.927 ; -1.181,-0.927 -1.181,-0.648 ; -1.181,-0.648 -1.181,-0.626 -0.724,-0.626 -0.724,-0.648 ; -1.181,-0.648 -0.724,-0.648 ; -1.181,0.66 -0.724,0.66 ; -1.181,0.66 -1.181,0.626 -0.724,0.626 -0.724,0.66 ; -1.181,0.66 -1.181,0.94 ; -1.181,0.94 -0.724,0.94 ; -1.181,0.94 -1.181,1.016 ; -1.181,1.016 -0.724,1.016 ; -1.181,1.016 -1.181,1.219 -0.724,1.219 -0.724,1.016 ; -0.724,-1.003 -0.724,-0.927 ; -0.724,-0.927 -0.724,-0.648 ; -0.724,0.66 -0.724,0.94 ; -0.724,0.94 -0.724,1.016 ; -0.229,-1.003 0.229,-1.003 ; -0.229,-1.003 -0.229,-1.206 0.229,-1.206 0.229,-1.003 ; -0.229,-1.003 -0.229,-0.927 ; -0.229,-0.927 -0.229,-0.648 ; -0.229,-0.927 0.229,-0.927 ; -0.229,-0.648 0.229,-0.648 ; -0.229,-0.648 -0.229,-0.626 0.229,-0.626 0.229,-0.648 ; -0.229,0.66 -0.229,0.626 0.229,0.626 0.229,0.66 ; -0.229,0.66 0.229,0.66 ; -0.229,0.66 -0.229,0.94 ; -0.229,0.94 0.229,0.94 ; -0.229,0.94 -0.229,1.016 ; -0.229,1.016 0.229,1.016 ; -0.229,1.016 -0.229,1.219 0.229,1.219 0.229,1.016 ; 0.229,-1.003 0.229,-0.927 ; 0.229,-0.927 0.229,-0.648 ; 0.229,0.66 0.229,0.94 ; 0.229,0.94 0.229,1.016 ; 0.724,-1.003 0.724,-0.927 ; 0.724,-1.003 1.181,-1.003 ; 0.724,-1.003 0.724,-1.206 1.181,-1.206 1.181,-1.003 ; 0.724,-0.927 1.181,-0.927 ; 0.724,-0.927 0.724,-0.648 ; 0.724,-0.648 1.181,-0.648 ; 0.724,-0.648 0.724,-0.626 1.181,-0.626 1.181,-0.648 ; 0.724,0.66 1.181,0.66 ; 0.724,0.66 0.724,0.626 1.181,0.626 1.181,0.66 ; 0.724,0.66 0.724,0.94 ; 0.724,0.94 1.181,0.94 ; 0.724,0.94 0.724,1.016 ; 0.724,1.016 1.181,1.016 ; 0.724,1.016 0.724,1.219 1.181,1.219 1.181,1.016 ; 1.181,-1.003 1.181,-0.927 ; 1.181,-0.927 1.181,-0.648 ; 1.181,0.66 1.181,0.94 ; 1.181,0.94 1.181,1.016 ; 1.212,-0.45 1.397,-0.635 ; 1.212,-0.45 1.212,0.45 ; 1.212,0.45 1.397,0.635 ; 1.397,-0.635 1.397,0.635
  text ".Designator" at -2.252,-0.226 h1
Top Courtyard:
  lines w0.05: -0.5,0 0.5,0 ; 0,-0.5 0,0.5 ; -1.7,-1.05 -1.49,-1.05 -1.49,-2.11 1.49,-2.11 1.49,-1.05 1.7,-1.05 1.7,1.05 1.49,1.05 1.49,2.11 -1.49,2.11 -1.49,1.05 -1.7,1.05 -1.7,-1.05
3D body "TPD4E001DBVR.step": height 1.45, standoff 0, extent -1.45,-1.4 1.45,1.4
